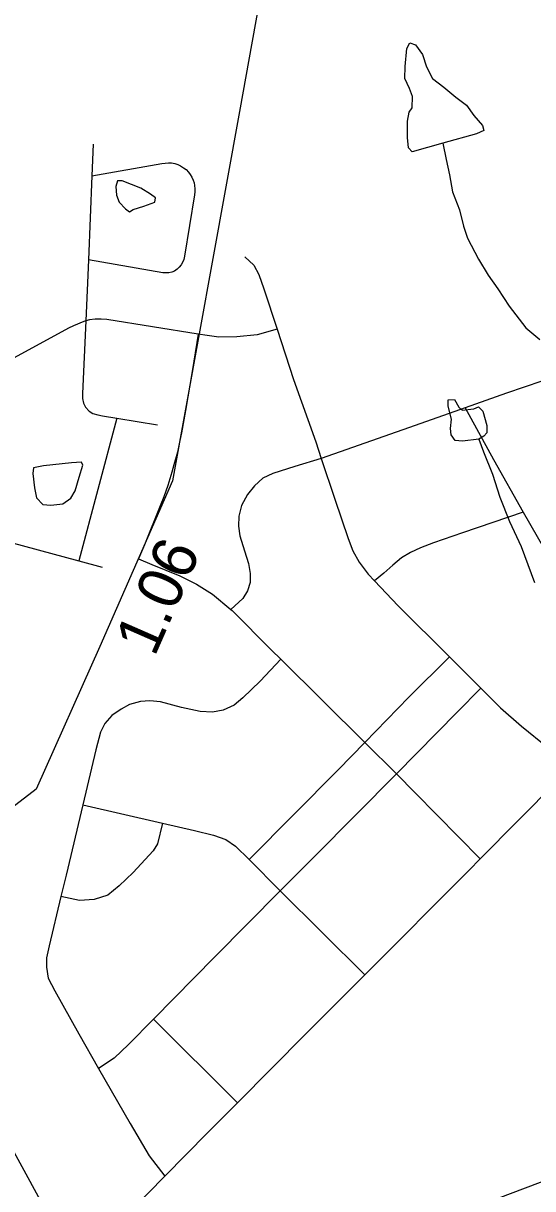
# Model space of a CAD drawing. Extents: x 1383679 to 1536984, y 460658 to 651027.
# Drawn here: x 1453635 to 1455065, y 466378 to 469651 of the extents above; entities that cross this region are included whole.
import ezdxf

# ---------------------------------------------------------------- set-up
doc = ezdxf.new("R2010")
doc.units = 0
for name, color, linetype in [('Default', 7, 'Continuous'), ('Exist Boundary Political City Limit New', 7, 'Continuous'), ('Exist Hydrographic Misc Water Feature', 7, 'Continuous'), ('Exist Road Non-System Type 51', 7, 'Continuous'), ('Exist Road Secondary Mileage Hundredths English Label', 7, 'Continuous'), ('Exist Road Secondary Type 51 Attributed', 7, 'Continuous'), ('Map Preparation Boundary City Limit Buffer Line', 7, 'Continuous')]:
    doc.layers.add(name, color=color, linetype=linetype)

msp = doc.modelspace()

# ---------------------------------------------------------------- linework, layer by layer
at = {"layer": 'Default'}
msp.add_lwpolyline([(1457347.8, 467401.6), (1457254.8, 467407.8), (1457099.6, 467426.4), (1456950.6, 467438.8), (1456845.1, 467432.6), (1456758.2, 467414), (1456690, 467320.9), (1456603.1, 467209.2), (1456503.9, 467085.1), (1456379.8, 466998.2), (1456255.6, 466948.6), (1456088.1, 466874.1), (1455827.5, 466805.9), (1455715.9, 466774.8), (1455635.1, 466706.6), (1455554.5, 466625.9), (1455442.8, 466551.4), (1455275.2, 466470.8), (1455120.1, 466408.7), (1454890.5, 466321.8)], dxfattribs=at)
at = {"layer": 'Exist Boundary Political City Limit New'}
msp.add_lwpolyline([(1457347.8, 467401.6), (1457254.8, 467407.8), (1457099.6, 467426.4), (1456950.6, 467438.8), (1456845.1, 467432.6), (1456758.2, 467414), (1456690, 467320.9), (1456603.1, 467209.2), (1456503.9, 467085.1), (1456379.8, 466998.2), (1456255.6, 466948.6), (1456088.1, 466874.1), (1455827.5, 466805.9), (1455715.9, 466774.8), (1455635.1, 466706.6), (1455554.5, 466625.9), (1455442.8, 466551.4), (1455275.2, 466470.8), (1455120.1, 466408.7), (1454890.5, 466321.8)], dxfattribs=at)
at = {"layer": 'Exist Hydrographic Misc Water Feature'}
for points in [[(1454812.7, 469314), (1454726.2, 469289.5), (1454716.5, 469301.2), (1454713, 469330), (1454713.8, 469376), (1454718.2, 469401.3), (1454726.5, 469413.4), (1454727, 469445.4), (1454719.4, 469467.7), (1454706, 469495.9), (1454706.6, 469529.5), (1454711.6, 469579.5), (1454719.9, 469595.7), (1454735.6, 469589.7), (1454755.2, 469563), (1454766.6, 469528.4), (1454784, 469496), (1454815.6, 469471.6), (1454849, 469443), (1454878.7, 469420.2), (1454900.1, 469391.9), (1454923.7, 469363.5), (1454927.4, 469349.5), (1454907.2, 469340.1), (1454812.7, 469314)], [(1454812.7, 469314), (1454822, 469267.9), (1454831.1, 469225), (1454840.2, 469177.3), (1454859.3, 469126.8), (1454870.5, 469080.7), (1454882, 469046.8), (1454912.8, 468987.9), (1454940, 468943), (1454967.4, 468904.7), (1454998.5, 468856.5), (1455045.4, 468795.7), (1455084.9, 468762.9)], [(1453964.5, 469187.3), (1453912.8, 469208), (1453898.9, 469208.3), (1453894.5, 469192), (1453896.1, 469168.1), (1453903.7, 469148.3), (1453921.3, 469129.9), (1453933.2, 469121.4), (1453943.4, 469127.8), (1453973.5, 469137.1), (1454003.6, 469147.9), (1454006, 469160.2), (1453992.2, 469170.3), (1453964.5, 469187.3)], [(1454913.6, 468483.2), (1454867.5, 468476.8), (1454847.5, 468478.8), (1454835.8, 468494.6), (1454834.1, 468512.7), (1454836.6, 468538.9), (1454827.3, 468575.2), (1454827.5, 468593.3), (1454845.7, 468594.6), (1454857.1, 468573), (1454867.1, 468564.6), (1454899.2, 468568), (1454913.2, 468573.5), (1454925.1, 468561.7), (1454936.4, 468521.3), (1454936, 468500.8), (1454927.8, 468491.2), (1454913.6, 468483.2)], [(1454913.6, 468483.2), (1454927, 468447.6), (1454951.9, 468384.8), (1454972.7, 468320.4), (1454999.4, 468251.7), (1455032.2, 468181.3), (1455070.4, 468080.4)], [(1453770, 468416.8), (1453691.6, 468407.7), (1453663.5, 468402.5), (1453661.3, 468386.2), (1453666.5, 468346.6), (1453672, 468317.8), (1453689.7, 468299.4), (1453711.7, 468297.3), (1453745.8, 468300.8), (1453768, 468316.7), (1453780.4, 468337.8), (1453791.2, 468376.2), (1453801.7, 468409.6), (1453797.9, 468417.9), (1453770, 468416.8)]]:
    msp.add_lwpolyline(points, dxfattribs=at)
at = {"layer": 'Exist Road Non-System Type 51'}
for p, q in [((1453831.4, 469310.8), (1453827.6, 469222.6)), ((1453827.6, 469222.6), (1453817.6, 468986.7)), ((1453817.6, 468986.7), (1453810.4, 468814.8)), ((1453897.4, 468542.1), (1453790.9, 468141.3)), ((1453897.4, 468542.1), (1454011.9, 468523.1)), ((1453470.9, 468227.3), (1453790.9, 468141.3)), ((1453790.9, 468141.3), (1453856.1, 468123.8)), ((1454830.9, 467871.8), (1454919.6, 467783.3)), ((1454357.8, 467865.1), (1454593.4, 467631)), ((1454593.4, 467631), (1454682.1, 467542.7)), ((1453801.9, 467456.1), (1454025.5, 467404.8)), ((1454268.5, 467302.5), (1454356.1, 467214.9)), ((1454356.1, 467214.9), (1454593.4, 466978.8)), ((1454000.2, 466854.3), (1454236.6, 466619.8)), ((1453608.4, 466482.2), (1453766, 466191.8))]:
    msp.add_line(p, q, dxfattribs=at)
for points in [[(1453827.6, 469222.6), (1454023.4, 469256.6), (1454033.4, 469257.9), (1454042.2, 469258.8), (1454051.2, 469258.4), (1454059.8, 469257), (1454068.8, 469254.3), (1454076.4, 469250.3), (1454084.9, 469244.9), (1454091.6, 469239.6), (1454098.4, 469232.8), (1454103.6, 469225.7), (1454108.1, 469218.5), (1454112.1, 469210.4), (1454114.4, 469202.3), (1454115.8, 469194.8), (1454116.2, 469186.2), (1454116.2, 469177.7), (1454115.8, 469168.8), (1454087.1, 468996.6), (1454085.4, 468987.2), (1454082.1, 468979.2), (1454077.6, 468972.4), (1454072.8, 468966.2), (1454066.5, 468960.3), (1454059.4, 468954.9), (1454052.1, 468952.2), (1454043.1, 468950), (1454035.1, 468949.6), (1454026.1, 468950), (1453817.6, 468986.7)], [(1453964.5, 469187.3), (1453912.8, 469208), (1453898.9, 469208.3), (1453894.5, 469192), (1453896.1, 469168.1), (1453903.7, 469148.3), (1453921.3, 469129.9), (1453933.2, 469121.4), (1453943.4, 469127.8), (1453973.5, 469137.1), (1454003.6, 469147.9), (1454006, 469160.2), (1453992.2, 469170.3), (1453964.5, 469187.3)], [(1454256.4, 468994.9), (1454281.8, 468971.7), (1454295.9, 468945.2), (1454310.1, 468904.8), (1454347.1, 468791.3)], [(1454126, 468777.6), (1453868.9, 468818.8), (1453853.1, 468819.8), (1453836.4, 468819.8), (1453820.6, 468817.9), (1453810.4, 468814.8)], [(1453810.4, 468814.8), (1453804.8, 468812.9), (1453776.1, 468801.1), (1453761.4, 468794.2), (1453536.6, 468672), (1453521.9, 468662.1), (1453508, 468651.2), (1453496.1, 468639.4), (1453487.4, 468627.6), (1453478.4, 468614.8), (1453472.5, 468602), (1453467.6, 468587.2), (1453464.6, 468571.4), (1453461.6, 468553.7), (1453460.6, 468532.9), (1453462.6, 468473.8)], [(1453810.4, 468814.8), (1453800.9, 468610.8), (1453800.9, 468597), (1453803.9, 468584.2), (1453809.8, 468572.4), (1453819.6, 468561.6), (1453830.4, 468554.7), (1453844.2, 468550.7), (1453857, 468548.8), (1453897.4, 468542.1)], [(1454347.1, 468791.3), (1454291.5, 468776.2), (1454233.9, 468770), (1454183.6, 468768.8), (1454151.1, 468773.8), (1454126, 468777.6)], [(1454347.1, 468791.3), (1454393.1, 468650.4), (1454456, 468475.1), (1454471.4, 468428.8)], [(1454126, 468777.6), (1454108.6, 468672.5), (1454089.8, 468563.3), (1454078.5, 468501), (1454074.4, 468479), (1454067.4, 468446.5), (1454057.6, 468410.6), (1454051.9, 468390.2), (1454040.6, 468353), (1454029.8, 468321), (1454019.5, 468295.2), (1453975.4, 468185.7), (1453958.1, 468146.7)], [(1455190.2, 468679.3), (1454991.4, 468611.9), (1454875.4, 468570.9)], [(1454875.4, 468570.9), (1454735.1, 468521.2), (1454471.4, 468428.8)], [(1454875.4, 468570.9), (1454954.6, 468425.6), (1455038.6, 468277.9)], [(1454471.4, 468428.8), (1454396.9, 468406), (1454335.6, 468386.4), (1454307.4, 468372.9), (1454284.1, 468352.1), (1454264.6, 468327.6), (1454247.4, 468296.9), (1454240.1, 468266.3), (1454238.9, 468238.1), (1454242.5, 468211.2), (1454256, 468169.5), (1454267, 468133.9), (1454271.9, 468105.8), (1454271.9, 468080), (1454264.6, 468056.8), (1454251.1, 468035.9), (1454217.9, 468004.2)], [(1454471.4, 468428.8), (1454509.8, 468314), (1454547.2, 468203.6), (1454560.4, 468169.1), (1454577.6, 468137.7), (1454602.9, 468104.2), (1454620.8, 468085.3)], [(1455038.6, 468277.9), (1454867.6, 468219.8), (1454786.4, 468192), (1454750.1, 468178.1), (1454721.5, 468165), (1454696.9, 468149.5), (1454672.1, 468129.4), (1454646.6, 468107), (1454620.8, 468085.3)], [(1455038.6, 468277.9), (1455116.4, 468141.2), (1455161.6, 468061.6), (1455186.2, 468022.4), (1455215.6, 467985.7), (1455256.1, 467939.1), (1455301.4, 467892.5), (1455364.9, 467837.6)], [(1453958.1, 468146.7), (1453995.6, 468131.2), (1454074.1, 468098.8), (1454121.2, 468075.8), (1454165.9, 468047.8), (1454217.9, 468004.2)], [(1454620.8, 468085.3), (1454687.1, 468015.1), (1454830.9, 467871.8)], [(1454217.9, 468004.2), (1454220.9, 468001.8), (1454331.9, 467890.8), (1454357.8, 467865.1)], [(1454830.9, 467871.8), (1454717.1, 467758.2), (1454593.4, 467631)], [(1454357.8, 467865.1), (1454299.4, 467803.6), (1454250.9, 467756.1), (1454226.6, 467735.7), (1454195.6, 467722.1), (1454165.5, 467716.2), (1454131.5, 467718.2), (1454079.1, 467729.8), (1454019.9, 467745.4), (1453989.9, 467748.3), (1453963.6, 467746.3), (1453932.6, 467737.7), (1453909.4, 467725), (1453883.1, 467706.6), (1453863.8, 467684.2), (1453851.1, 467660), (1453838.5, 467610.5), (1453801.9, 467456.1)], [(1454919.6, 467783.3), (1454853.1, 467716), (1454682.1, 467542.7)], [(1454919.6, 467783.3), (1454974.9, 467728.3), (1455033.6, 467676.7), (1455107.6, 467616.8), (1455178.5, 467569.2)], [(1454593.4, 467631), (1454518.6, 467554.8), (1454268.5, 467302.5)], [(1454682.1, 467542.7), (1454452.8, 467312.3), (1454356.1, 467214.9)], [(1454682.1, 467542.7), (1454735.2, 467490), (1454917.8, 467304.9)], [(1455178.5, 467569.2), (1455132.1, 467521), (1454917.8, 467304.9)], [(1453801.9, 467456.1), (1453755, 467258.3), (1453740.6, 467198.4)], [(1454025.5, 467404.8), (1454011.6, 467346.3), (1453999.4, 467326.8), (1453942.8, 467266), (1453903.6, 467228.2), (1453872.5, 467202.6), (1453833.4, 467190.4), (1453792.2, 467187.8), (1453740.6, 467198.4)], [(1454025.5, 467404.8), (1454115.4, 467384.2), (1454168.9, 467370.6), (1454203.4, 467358.9), (1454230.6, 467340.4), (1454268.5, 467302.5)], [(1454917.8, 467304.9), (1454886.1, 467272.9), (1454593.4, 466978.8)], [(1454356.1, 467214.9), (1454172.1, 467029.2), (1454000.2, 466854.3)], [(1453740.6, 467198.4), (1453707.5, 467060.3), (1453699.8, 467026.4), (1453699.8, 467000.2), (1453704.6, 466969.2), (1453723, 466934.2), (1453790.9, 466812.9), (1453846.2, 466716.1)], [(1454593.4, 466978.8), (1454427.4, 466812.1), (1454236.6, 466619.8)], [(1454000.2, 466854.3), (1453930.1, 466783.2), (1453889.8, 466745.2), (1453846.2, 466716.1)], [(1453846.2, 466716.1), (1453934.6, 466561.6), (1453987.9, 466470.4), (1454032.6, 466413.3)], [(1454236.6, 466619.8), (1454152.2, 466534.8), (1454032.6, 466413.3)], [(1454032.6, 466413.3), (1453890.6, 466269), (1453886.9, 466265.4)]]:
    msp.add_lwpolyline(points, dxfattribs=at)
at = {"layer": 'Exist Road Secondary Type 51 Attributed'}
msp.add_lwpolyline([(1454386.7, 470599.1), (1454384.2, 470194.1), (1454241.6, 469402.7), (1454054, 468365.8), (1453850.1, 467900.4), (1453670.6, 467500.4), (1453564.6, 467418.7), (1453336.2, 467402.4), (1452699.9, 467475.9), (1452438.9, 467500.4), (1452275.8, 467451.4), (1451404.6, 467124.8)], dxfattribs=at)
at = {"layer": 'Map Preparation Boundary City Limit Buffer Line'}
msp.add_lwpolyline([(1457347.8, 467401.6), (1457254.8, 467407.8), (1457099.6, 467426.4), (1456950.6, 467438.8), (1456845.1, 467432.6), (1456758.2, 467414), (1456690, 467320.9), (1456603.1, 467209.2), (1456503.9, 467085.1), (1456379.8, 466998.2), (1456255.6, 466948.6), (1456088.1, 466874.1), (1455827.5, 466805.9), (1455715.9, 466774.8), (1455635.1, 466706.6), (1455554.5, 466625.9), (1455442.8, 466551.4), (1455275.2, 466470.8), (1455120.1, 466408.7), (1454890.5, 466321.8)], dxfattribs=at)
msp.add_lwpolyline([(1457347.8, 467401.6), (1457254.8, 467407.8), (1457099.6, 467426.4), (1456950.6, 467438.8), (1456845.1, 467432.6), (1456758.2, 467414), (1456690, 467320.9), (1456603.1, 467209.2), (1456503.9, 467085.1), (1456379.8, 466998.2), (1456255.6, 466948.6), (1456088.1, 466874.1), (1455827.5, 466805.9), (1455715.9, 466774.8), (1455635.1, 466706.6), (1455554.5, 466625.9), (1455442.8, 466551.4), (1455275.2, 466470.8), (1455120.1, 466408.7), (1454890.5, 466321.8)], dxfattribs=at)

# ---------------------------------------------------------------- texts
at = {"layer": 'Exist Road Secondary Mileage Hundredths English Label'}
msp.add_text('1.06', height=125, rotation=66.3377, dxfattribs=at).set_placement((1454003, 467869))

doc.saveas('drawing.dxf')
